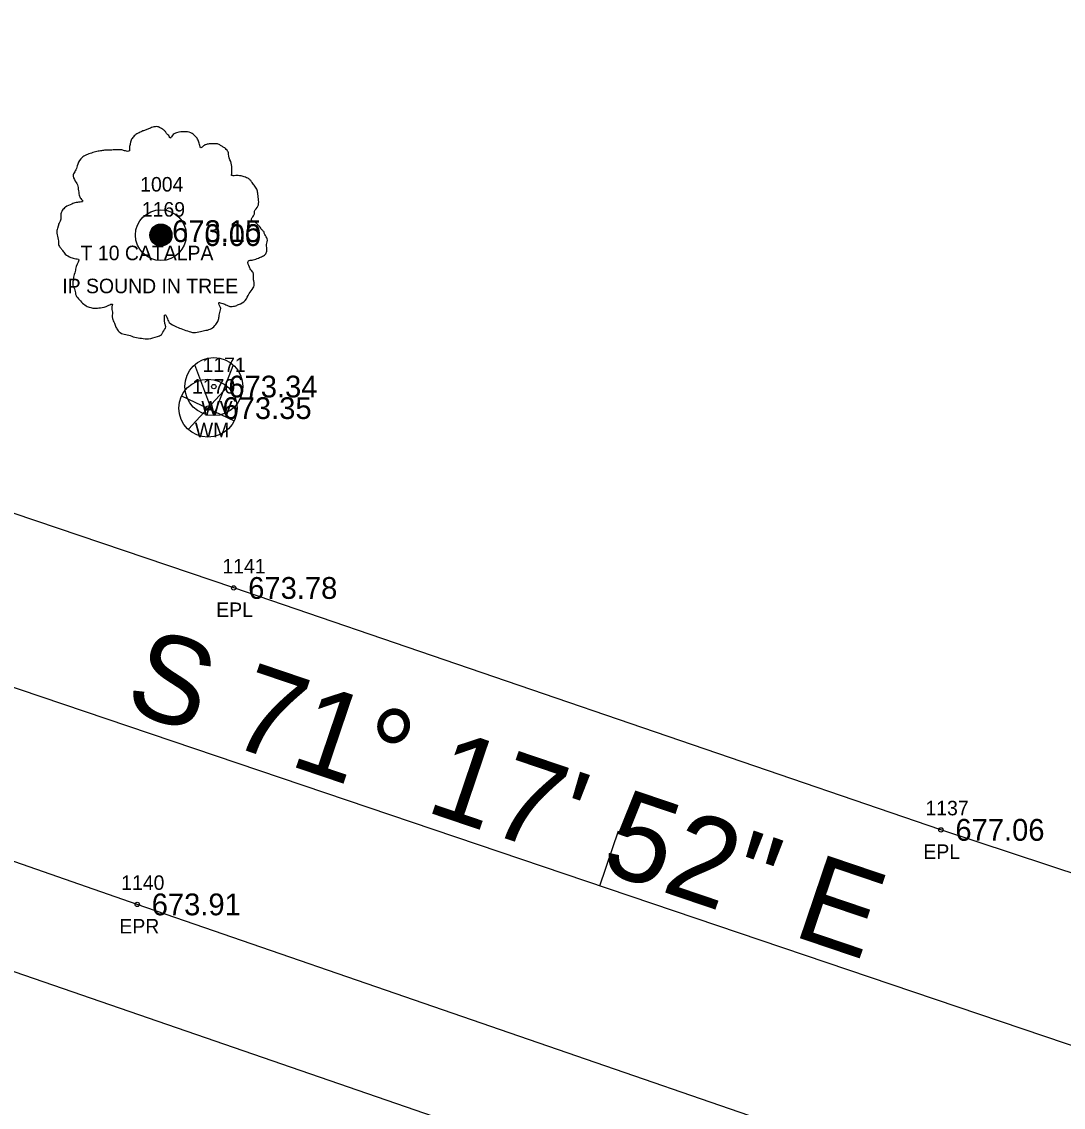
# Model space of a CAD drawing. Extents: x 1655137 to 1657928, y 1003994 to 1005407.
# Drawn here: x 1656708.9 to 1656780.6, y 1004485.2 to 1004559.9 of the extents above; entities that cross this region are included whole.
import ezdxf

# ---------------------------------------------------------------- set-up
doc = ezdxf.new("R2010")
doc.units = 0
for name, color, linetype in [('RD_EX_DV_Prop_txCode', 7, 'Continuous'), ('RD_EX_DV_PropPin', 7, 'Continuous'), ('RD_EX_Road', 7, 'Continuous'), ('RD_EX_Road_txCode', 7, 'Continuous'), ('RD_EX_TX_DV_Prop_ELEV', 7, 'Continuous'), ('RD_EX_TX_Road_ELEV', 7, 'Continuous'), ('RD_EX_TX_UT_ELEV', 7, 'Continuous'), ('RD_EX_TX_VEG_ELEV', 7, 'Continuous'), ('RD_EX_UT', 7, 'Continuous'), ('RD_EX_UT_txCode', 7, 'Continuous'), ('RD_EX_VEG', 7, 'Continuous'), ('RD_EX_VEG_txCode', 7, 'Continuous'), ('RD_HC_Cl', 7, 'Continuous'), ('RD_HC_Data', 7, 'Continuous'), ('RD_HC_Data_Tic', 7, 'Continuous'), ('RD_SMD_Locator', 7, 'Continuous')]:
    doc.layers.add(name, color=color, linetype=linetype)

msp = doc.modelspace()

# ---------------------------------------------------------------- linework, layer by layer
at = {"layer": 'RD_EX_DV_PropPin'}
for p, q in [((1656717.701, 1004545.018), (1656717.701, 1004545.41)), ((1656717.736, 1004544.916), (1656717.736, 1004545.512)), ((1656717.771, 1004544.844), (1656717.771, 1004545.584)), ((1656717.806, 1004544.787), (1656717.806, 1004545.641)), ((1656717.841, 1004544.74), (1656717.841, 1004545.688)), ((1656717.876, 1004544.699), (1656717.876, 1004545.729)), ((1656717.911, 1004544.663), (1656717.911, 1004545.765)), ((1656717.946, 1004544.632), (1656717.946, 1004545.796)), ((1656717.981, 1004544.604), (1656717.981, 1004545.824)), ((1656718.016, 1004544.579), (1656718.016, 1004545.849)), ((1656718.051, 1004544.558), (1656718.051, 1004545.87)), ((1656718.086, 1004544.538), (1656718.086, 1004545.89)), ((1656718.121, 1004544.521), (1656718.121, 1004545.907)), ((1656718.156, 1004544.506), (1656718.156, 1004545.922)), ((1656718.191, 1004544.494), (1656718.191, 1004545.934)), ((1656718.226, 1004544.483), (1656718.226, 1004545.945)), ((1656718.261, 1004544.473), (1656718.261, 1004545.955)), ((1656718.296, 1004544.466), (1656718.296, 1004545.962)), ((1656718.331, 1004544.46), (1656718.331, 1004545.968)), ((1656718.366, 1004544.456), (1656718.366, 1004545.972)), ((1656718.401, 1004544.454), (1656718.401, 1004545.974)), ((1656718.436, 1004544.453), (1656718.436, 1004545.975)), ((1656718.471, 1004544.454), (1656718.471, 1004545.974)), ((1656718.506, 1004544.456), (1656718.506, 1004545.972)), ((1656718.541, 1004544.46), (1656718.541, 1004545.968)), ((1656718.576, 1004544.466), (1656718.576, 1004545.962)), ((1656718.611, 1004544.473), (1656718.611, 1004545.955)), ((1656718.646, 1004544.483), (1656718.646, 1004545.945)), ((1656718.681, 1004544.494), (1656718.681, 1004545.934)), ((1656718.716, 1004544.506), (1656718.716, 1004545.922)), ((1656718.752, 1004544.521), (1656718.752, 1004545.907)), ((1656718.787, 1004544.538), (1656718.787, 1004545.89)), ((1656718.822, 1004544.558), (1656718.822, 1004545.87)), ((1656718.857, 1004544.579), (1656718.857, 1004545.849)), ((1656718.892, 1004544.604), (1656718.892, 1004545.824)), ((1656718.927, 1004544.632), (1656718.927, 1004545.796)), ((1656718.962, 1004544.663), (1656718.962, 1004545.765)), ((1656718.997, 1004544.699), (1656718.997, 1004545.729)), ((1656719.032, 1004544.74), (1656719.032, 1004545.688)), ((1656719.067, 1004544.787), (1656719.067, 1004545.641)), ((1656719.102, 1004544.844), (1656719.102, 1004545.584)), ((1656719.137, 1004544.916), (1656719.137, 1004545.512)), ((1656719.172, 1004545.018), (1656719.172, 1004545.41))]:
    msp.add_line(p, q, dxfattribs=at)
for radius in [1.75, 0.761]:
    msp.add_circle((1656718.436, 1004545.214), radius, dxfattribs=at)
at = {"layer": 'RD_EX_Road'}
for points in [[(1657064.386, 1004409.093), (1657015.673, 1004424.638), (1656965.82, 1004440.601), (1656917.987, 1004455.951), (1656868.502, 1004471.858), (1656826.533, 1004486.061), (1656801.74, 1004494.508), (1656772.14, 1004504.273), (1656723.449, 1004520.924), (1656674.937, 1004537.34), (1656626.5, 1004553.879), (1656578.266, 1004569.524), (1656529.181, 1004584.752), (1656481.495, 1004600.509), (1656432.674, 1004617.136), (1656404.342, 1004625.816)], [(1657057.771, 1004388.922), (1657009.7, 1004404.075), (1656958.177, 1004419.835), (1656956.487, 1004419.667), (1656924.827, 1004429.547), (1656916.506, 1004432.799), (1656911.189, 1004434.68), (1656862.464, 1004450.207), (1656813.53, 1004466.421), (1656765.511, 1004482.334), (1656716.805, 1004499.141), (1656668.597, 1004515.926), (1656620.24, 1004532.541), (1656571.717, 1004548.369), (1656523.305, 1004563.773), (1656474.365, 1004580.294), (1656426.433, 1004596.82), (1656398.222, 1004606.78)]]:
    msp.add_lwpolyline(points, dxfattribs=at)
at = {"layer": 'RD_EX_UT'}
for p, q in [((1656722.082, 1004532.796), (1656720.778, 1004536.279)), ((1656722.082, 1004532.796), (1656723.404, 1004536.242)), ((1656720.327, 1004531.846), (1656722.995, 1004534.743)), ((1656719.846, 1004534.141), (1656723.477, 1004532.429))]:
    msp.add_line(p, q, dxfattribs=at)
for centre in [(1656722.082, 1004534.789), (1656721.679, 1004533.304)]:
    msp.add_circle(centre, 2, dxfattribs=at)
at = {"layer": 'RD_EX_VEG'}
msp.add_lwpolyline([(1656891.075, 1004405.367), (1656915.129, 1004420.396), (1656763.49, 1004475.476), (1656570.005, 1004542.196), (1656467.816, 1004565.095), (1656367.545, 1004594.624), (1656280.899, 1004634.634), (1656273.57, 1004608.648)], dxfattribs=at)
for centre, radius in [((1656718.211, 1004545.487), 0.25), ((1656718.198, 1004545.468), 0.0001)]:
    msp.add_circle(centre, radius, dxfattribs=at)
for points in [[(1656718.343, 1004552.654), (1656718.043, 1004552.679), (1656717.718, 1004552.579), (1656717.468, 1004552.479), (1656717.243, 1004552.404), (1656717.018, 1004552.304), (1656716.718, 1004552.129), (1656716.494, 1004551.929), (1656716.369, 1004551.679), (1656716.319, 1004551.454), (1656716.269, 1004551.18), (1656716.269, 1004551.005), (1656716.144, 1004550.98), (1656715.994, 1004551.005), (1656715.744, 1004551.08), (1656715.494, 1004551.08), (1656715.244, 1004551.08), (1656714.894, 1004551.055), (1656714.544, 1004551.055), (1656714.27, 1004551.005), (1656713.945, 1004550.955), (1656713.57, 1004550.83), (1656713.22, 1004550.705), (1656712.92, 1004550.455), (1656712.67, 1004549.98), (1656712.545, 1004549.63), (1656712.395, 1004549.38), (1656712.545, 1004548.931), (1656712.72, 1004548.581), (1656712.745, 1004548.381), (1656712.82, 1004547.956), (1656712.92, 1004547.731), (1656713.045, 1004547.531), (1656712.97, 1004547.506), (1656712.595, 1004547.456), (1656712.295, 1004547.356), (1656711.871, 1004547.131), (1656711.646, 1004546.906), (1656711.546, 1004546.582), (1656711.521, 1004546.232), (1656711.421, 1004546.032), (1656711.346, 1004545.757), (1656711.321, 1004545.682), (1656711.271, 1004545.357), (1656711.371, 1004544.907), (1656711.396, 1004544.557), (1656711.521, 1004544.333), (1656711.671, 1004544.158), (1656711.846, 1004543.908), (1656712.245, 1004543.683), (1656712.57, 1004543.583), (1656712.77, 1004543.558), (1656712.595, 1004543.058), (1656712.545, 1004542.708), (1656712.42, 1004542.308), (1656712.42, 1004542.234), (1656712.37, 1004541.759), (1656712.52, 1004541.434), (1656712.595, 1004541.059), (1656712.77, 1004540.834), (1656713.045, 1004540.534), (1656713.37, 1004540.309), (1656713.87, 1004540.184), (1656714.27, 1004540.209), (1656714.844, 1004540.384), (1656715.094, 1004540.459), (1656715.069, 1004540.284), (1656715.094, 1004539.909), (1656715.094, 1004539.485), (1656715.244, 1004539.16), (1656715.344, 1004538.885), (1656715.494, 1004538.635), (1656715.819, 1004538.41), (1656716.219, 1004538.335), (1656716.643, 1004538.185), (1656717.093, 1004538.11), (1656717.593, 1004538.085), (1656718.193, 1004538.235), (1656718.468, 1004538.36), (1656718.568, 1004538.535), (1656718.768, 1004538.91), (1656718.718, 1004539.135), (1656718.743, 1004539.735), (1656718.842, 1004539.56), (1656719.017, 1004539.21), (1656719.517, 1004538.91), (1656719.917, 1004538.735), (1656720.392, 1004538.585), (1656720.692, 1004538.51), (1656721.166, 1004538.585), (1656721.541, 1004538.66), (1656721.916, 1004538.785), (1656722.216, 1004539.06), (1656722.391, 1004539.335), (1656722.441, 1004539.61), (1656722.516, 1004539.984), (1656722.566, 1004540.159)], [(1656722.566, 1004540.159), (1656722.491, 1004540.334), (1656722.441, 1004540.584), (1656722.516, 1004540.559), (1656722.691, 1004540.509), (1656722.966, 1004540.384), (1656723.191, 1004540.309), (1656723.515, 1004540.334), (1656723.79, 1004540.434), (1656724.24, 1004540.709), (1656724.515, 1004541.184), (1656724.79, 1004541.584), (1656724.865, 1004541.909), (1656724.815, 1004542.134), (1656724.79, 1004542.633), (1656724.59, 1004542.883), (1656724.54, 1004543.008), (1656724.44, 1004543.408), (1656724.515, 1004543.458), (1656724.79, 1004543.508), (1656725.165, 1004543.633), (1656725.44, 1004543.758), (1656725.665, 1004543.933), (1656725.739, 1004544.158), (1656725.715, 1004544.557), (1656725.764, 1004544.957), (1656725.69, 1004545.107), (1656725.59, 1004545.257), (1656725.515, 1004545.457), (1656725.365, 1004545.607), (1656725.265, 1004545.757), (1656725.165, 1004545.857), (1656725.04, 1004546.007), (1656724.865, 1004546.132), (1656724.715, 1004546.182), (1656724.665, 1004546.332), (1656724.815, 1004546.532), (1656724.865, 1004546.632), (1656724.89, 1004546.856), (1656725.115, 1004547.206), (1656725.165, 1004547.606), (1656725.115, 1004548.031), (1656725.065, 1004548.306), (1656724.915, 1004548.581), (1656724.715, 1004548.831), (1656724.59, 1004549.006), (1656724.415, 1004549.13), (1656724.09, 1004549.255), (1656723.84, 1004549.305), (1656723.49, 1004549.305), (1656723.291, 1004549.355), (1656723.316, 1004549.405), (1656723.316, 1004549.555), (1656723.316, 1004549.83), (1656723.241, 1004550.28), (1656723.091, 1004550.78), (1656723.091, 1004550.805), (1656722.991, 1004551.055), (1656722.766, 1004551.255), (1656722.591, 1004551.354), (1656722.391, 1004551.479), (1656722.141, 1004551.504), (1656721.841, 1004551.504), (1656721.566, 1004551.454), (1656721.366, 1004551.354), (1656721.191, 1004551.23), (1656721.116, 1004551.379), (1656721.017, 1004551.679), (1656720.967, 1004551.829), (1656720.817, 1004552.004), (1656720.592, 1004552.204), (1656720.142, 1004552.329), (1656719.517, 1004552.254), (1656719.217, 1004552.054), (1656719.067, 1004551.879), (1656719.017, 1004552.004), (1656718.817, 1004552.204), (1656718.718, 1004552.379), (1656718.543, 1004552.504), (1656718.393, 1004552.604), (1656718.293, 1004552.654)]]:
    msp.add_spline(points, degree=3, dxfattribs=at)
at = {"layer": 'RD_HC_Cl'}
msp.add_line((1656624.525, 1004542.444), (1656857.937, 1004463.429), dxfattribs=at)
at = {"layer": 'RD_HC_Data_Tic'}
msp.add_line((1656748.662, 1004500.421), (1656749.944, 1004504.21), dxfattribs=at)
at = {"layer": 'RD_SMD_Locator'}
for centre in [(1656718.211, 1004545.487), (1656718.436, 1004545.214), (1656722.082, 1004534.789), (1656721.679, 1004533.304), (1656723.449, 1004520.924), (1656772.14, 1004504.273), (1656716.805, 1004499.141)]:
    msp.add_circle(centre, 0.15, dxfattribs=at)

# ---------------------------------------------------------------- texts
at = {"layer": 'RD_EX_DV_Prop_txCode'}
for s, p in [('1004', (1656717.011, 1004548.214)), ('IP SOUND IN TREE', (1656711.645, 1004541.214))]:
    msp.add_text(s, height=1, dxfattribs=at).set_placement(p)
at = {"layer": 'RD_EX_Road_txCode'}
for s, p in [('1141', (1656722.67, 1004521.924)), ('EPL', (1656722.245, 1004518.924)), ('1137', (1656771.077, 1004505.273)), ('EPL', (1656770.935, 1004502.273)), ('1140', (1656715.703, 1004500.141)), ('EPR', (1656715.577, 1004497.141))]:
    msp.add_text(s, height=1, dxfattribs=at).set_placement(p)
at = {"layer": 'RD_EX_TX_DV_Prop_ELEV'}
msp.add_text('0.00', height=1.5, dxfattribs=at).set_placement((1656721.436, 1004544.464))
at = {"layer": 'RD_EX_TX_Road_ELEV'}
for s, p in [('673.78', (1656724.449, 1004520.174)), ('677.06', (1656773.14, 1004503.523)), ('673.91', (1656717.805, 1004498.391))]:
    msp.add_text(s, height=1.5, dxfattribs=at).set_placement(p)
at = {"layer": 'RD_EX_TX_UT_ELEV'}
for s, p in [('673.34', (1656723.082, 1004534.039)), ('673.35', (1656722.679, 1004532.554))]:
    msp.add_text(s, height=1.5, dxfattribs=at).set_placement(p)
at = {"layer": 'RD_EX_TX_VEG_ELEV'}
msp.add_text('673.15', height=1.5, dxfattribs=at).set_placement((1656719.211, 1004544.737))
at = {"layer": 'RD_EX_UT_txCode'}
for s, p in [('1171', (1656721.302, 1004535.789)), ('1170', (1656720.577, 1004534.304)), ('WV', (1656721.223, 1004532.789)), ('WM', (1656720.774, 1004531.304))]:
    msp.add_text(s, height=1, dxfattribs=at).set_placement(p)
at = {"layer": 'RD_EX_VEG_txCode'}
for s, p in [('1169', (1656717.124, 1004546.487)), ('T 10 CATALPA', (1656712.912, 1004543.487))]:
    msp.add_text(s, height=1, dxfattribs=at).set_placement(p)
at = {"layer": 'RD_HC_Data'}
msp.add_text('S 71%%d 17\' 52" E', height=6, rotation=341.29776, dxfattribs=at).set_placement((1656715.747, 1004512.619))

doc.saveas('drawing.dxf')
